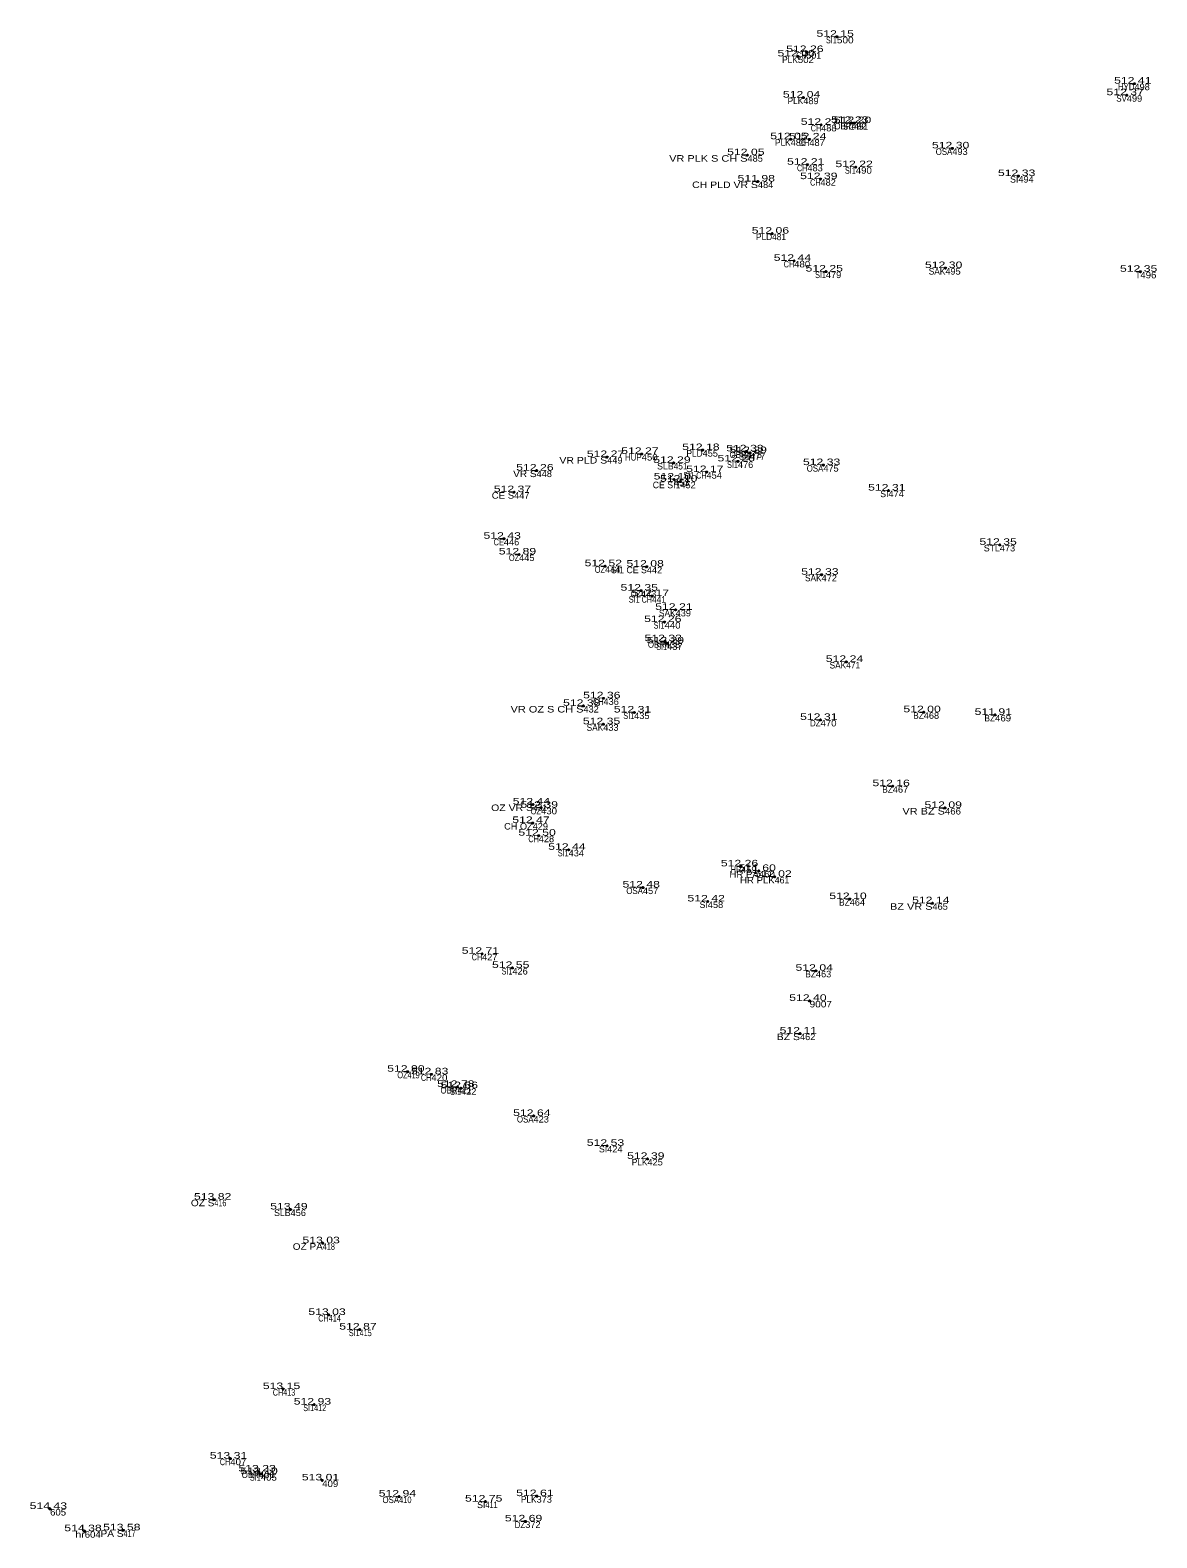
# Model space of a CAD drawing. Extents: x -643086 to -639283, y -1131805 to -1123269.
# Drawn here: x -639403.7 to -639352, y -1123478.6 to -1123409.5 of the extents above; entities that cross this region are included whole.
import ezdxf
from ezdxf.enums import TextEntityAlignment as Align

# ---------------------------------------------------------------- set-up
doc = ezdxf.new("R2010")
doc.units = 0
doc.header["$LTSCALE"] = 0.12
doc.header["$PDMODE"] = 32
doc.header["$PDSIZE"] = 0.06
for name, color, linetype in [('1', 7, 'Continuous'), ('2', 7, 'Continuous'), ('3', 7, 'Continuous'), ('4', 7, 'Continuous')]:
    doc.layers.add(name, color=color, linetype=linetype)

msp = doc.modelspace()

# ---------------------------------------------------------------- linework, layer by layer
at = {"layer": '1'}
for p in [(-639366.68, -1123409.77), (-639368.47, -1123410.67), (-639368.07, -1123410.47), (-639353.02, -1123411.92), (-639368.22, -1123412.56), (-639353.37, -1123412.45), (-639367.4, -1123413.81), (-639366.01, -1123413.72), (-639365.88, -1123413.73), (-639368.8, -1123414.47), (-639367.94, -1123414.48), (-639361.38, -1123414.89), (-639370.78, -1123415.2), (-639368.03, -1123415.64), (-639367.43, -1123416.3), (-639365.81, -1123415.75), (-639358.35, -1123416.16), (-639370.3, -1123416.41), (-639369.65, -1123418.8), (-639368.64, -1123420.05), (-639367.18, -1123420.54), (-639361.7, -1123420.38), (-639352.75, -1123420.55), (-639372.84, -1123428.73), (-639370.82, -1123428.79), (-639377.22, -1123429.05), (-639375.64, -1123428.91), (-639374.17, -1123429.32), (-639371.22, -1123429.25), (-639370.67, -1123428.87), (-639367.3, -1123429.42), (-639380.46, -1123429.67), (-639374.15, -1123430.08), (-639373.86, -1123430.18), (-639372.66, -1123429.74), (-639381.49, -1123430.66), (-639364.31, -1123430.59), (-639381.96, -1123432.8), (-639381.26, -1123433.52), (-639359.2, -1123433.08), (-639377.32, -1123434.06), (-639375.4, -1123434.08), (-639367.38, -1123434.45), (-639375.67, -1123435.18), (-639375.16, -1123435.43), (-639374.08, -1123436.06), (-639374.59, -1123436.62), (-639374.57, -1123437.5), (-639374.47, -1123437.6), (-639366.25, -1123438.45), (-639378.31, -1123440.47), (-639377.39, -1123440.12), (-639375.98, -1123440.77), (-639367.43, -1123441.11), (-639362.69, -1123440.76), (-639359.42, -1123440.88), (-639377.4, -1123441.31), (-639364.11, -1123444.15), (-639380.62, -1123444.99), (-639380.26, -1123445.14), (-639361.72, -1123445.15), (-639380.64, -1123445.84), (-639380.36, -1123446.42), (-639378.99, -1123447.07), (-639371.07, -1123447.83), (-639370.26, -1123448.04), (-639375.58, -1123448.8), (-639369.53, -1123448.31), (-639372.6, -1123449.44), (-639366.09, -1123449.33), (-639362.29, -1123449.52), (-639382.96, -1123451.84), (-639381.57, -1123452.49), (-639367.64, -1123452.62), (-639367.93, -1123454), (-639368.37, -1123455.5), (-639386.38, -1123457.25), (-639385.29, -1123457.37), (-639384.09, -1123457.95), (-639383.93, -1123458.01), (-639380.6, -1123459.28), (-639377.22, -1123460.65), (-639375.37, -1123461.25), (-639395.25, -1123463.12), (-639391.75, -1123463.57), (-639390.27, -1123465.12), (-639390, -1123468.41), (-639388.58, -1123469.08), (-639392.09, -1123471.81), (-639390.67, -1123472.52), (-639394.52, -1123475), (-639393.21, -1123475.59), (-639393.12, -1123475.71), (-639390.3, -1123476), (-639386.77, -1123476.74), (-639382.81, -1123476.97), (-639380.46, -1123476.72), (-639402.79, -1123477.31), (-639380.98, -1123477.88), (-639401.2, -1123478.33), (-639399.42, -1123478.29)]:
    msp.add_point(p, dxfattribs=at)

# ---------------------------------------------------------------- texts
at = {"layer": '2'}
for s, width, p in [('500', 1.15, (-639366.68, -1123410.07)), ('502', 1.1, (-639368.47, -1123410.97)), ('498', 1.05, (-639353.02, -1123412.22)), ('489', 1.05, (-639368.22, -1123412.86)), ('499', 1.05, (-639353.37, -1123412.75)), ('488', 1.05, (-639367.4, -1123414.11)), ('492', 1.05, (-639366.01, -1123414.02)), ('491', 0.95, (-639365.88, -1123414.03)), ('486', 1.05, (-639368.8, -1123414.77)), ('487', 1.05, (-639367.94, -1123414.78)), ('493', 1.05, (-639361.38, -1123415.19)), ('485', 1.05, (-639370.78, -1123415.5)), ('483', 1.05, (-639368.03, -1123415.94)), ('482', 1.05, (-639367.43, -1123416.6)), ('490', 1.1, (-639365.81, -1123416.05)), ('494', 1.05, (-639358.35, -1123416.46)), ('484', 1.05, (-639370.3, -1123416.71)), ('481', 0.95, (-639369.65, -1123419.1)), ('480', 1.1, (-639368.64, -1123420.35)), ('495', 1.05, (-639361.7, -1123420.68)), ('479', 1.05, (-639367.18, -1123420.84)), ('496', 1.1, (-639352.75, -1123420.85)), ('455', 1.05, (-639372.84, -1123429.03)), ('478', 1.05, (-639370.82, -1123429.09)), ('449', 1.05, (-639377.22, -1123429.35)), ('450', 1.1, (-639375.64, -1123429.21)), ('451', 0.95, (-639374.17, -1123429.62)), ('476', 1.05, (-639371.22, -1123429.55)), ('477', 1.05, (-639370.67, -1123429.17)), ('475', 1.05, (-639367.3, -1123429.72)), ('448', 1.05, (-639380.46, -1123429.97)), ('453', 1.05, (-639374.15, -1123430.38)), ('452', 1.05, (-639373.86, -1123430.48)), ('454', 1.05, (-639372.66, -1123430.04)), ('447', 1.05, (-639381.49, -1123430.96)), ('474', 1.05, (-639364.31, -1123430.89)), ('446', 1.05, (-639381.96, -1123433.1)), ('445', 1.05, (-639381.26, -1123433.82)), ('473', 1.05, (-639359.2, -1123433.38)), ('444', 1.05, (-639377.32, -1123434.36)), ('442', 1.05, (-639375.4, -1123434.38)), ('472', 1.05, (-639367.38, -1123434.75)), ('443', 1.05, (-639375.67, -1123435.48)), ('441', 0.95, (-639375.16, -1123435.73)), ('439', 1.05, (-639374.08, -1123436.36)), ('440', 1.1, (-639374.59, -1123436.92)), ('438', 1.05, (-639374.57, -1123437.8)), ('437', 1.05, (-639374.47, -1123437.9)), ('471', 0.95, (-639366.25, -1123438.75)), ('432', 1.05, (-639378.31, -1123440.77)), ('436', 1.05, (-639377.39, -1123440.42)), ('435', 1.05, (-639375.98, -1123441.07)), ('470', 1.1, (-639367.43, -1123441.41)), ('468', 1.05, (-639362.69, -1123441.06)), ('469', 1.1, (-639359.42, -1123441.18)), ('433', 1.05, (-639377.4, -1123441.61)), ('467', 1.05, (-639364.11, -1123444.45)), ('431', 0.95, (-639380.62, -1123445.29)), ('430', 1.1, (-639380.26, -1123445.44)), ('466', 1.1, (-639361.72, -1123445.45)), ('429', 1.05, (-639380.64, -1123446.14)), ('428', 1.05, (-639380.36, -1123446.72)), ('434', 1.05, (-639378.99, -1123447.37)), ('459', 1.05, (-639371.07, -1123448.13)), ('460', 1.1, (-639370.26, -1123448.34)), ('457', 1.05, (-639375.58, -1123449.1)), ('458', 1.05, (-639372.6, -1123449.74)), ('464', 1.05, (-639366.09, -1123449.63)), ('465', 1.05, (-639362.29, -1123449.82)), ('427', 1.05, (-639382.96, -1123452.14)), ('426', 1.05, (-639381.57, -1123452.79)), ('463', 1.05, (-639367.64, -1123452.92)), ('9007', 1.15, (-639367.93, -1123454.3)), ('462', 1.05, (-639368.37, -1123455.8)), ('419', 0.8, (-639386.38, -1123457.55)), ('420', 1.1, (-639385.29, -1123457.67)), ('421', 0.95, (-639384.09, -1123458.25)), ('422', 1.05, (-639383.93, -1123458.31)), ('423', 1.05, (-639380.6, -1123459.58)), ('424', 1.05, (-639377.22, -1123460.95)), ('425', 1.05, (-639375.37, -1123461.55)), ('416', 0.8, (-639395.25, -1123463.42)), ('456', 1.05, (-639391.75, -1123463.87)), ('418', 0.8, (-639390.27, -1123465.42)), ('414', 0.8, (-639390, -1123468.71)), ('415', 0.8, (-639388.58, -1123469.38)), ('413', 0.8, (-639392.09, -1123472.11)), ('412', 0.8, (-639390.67, -1123472.82)), ('407', 1.1, (-639394.52, -1123475.3)), ('406', 1.1, (-639393.21, -1123475.89)), ('405', 1.1, (-639393.12, -1123476.01)), ('409', 1.1, (-639390.3, -1123476.3)), ('410', 0.85, (-639386.77, -1123477.04)), ('411', 0.7, (-639382.81, -1123477.27)), ('373', 1.05, (-639380.46, -1123477.02)), ('605', 1.1, (-639402.79, -1123477.61)), ('372', 1.05, (-639380.98, -1123478.18)), ('604', 1.1, (-639401.2, -1123478.63)), ('417', 0.8, (-639399.42, -1123478.59))]:
    msp.add_text(s, height=0.3, dxfattribs=dict(at, width=width)).set_placement(p)
for s, p in [('501', (-639368.07, -1123410.77)), ('461', (-639369.53, -1123448.61))]:
    msp.add_text(s, height=0.3, dxfattribs=at).set_placement(p)
at = {"layer": '3', "width": 1.4}
for s, p in [('512 15 ', (-639366.68, -1123409.77)), ('512 00 ', (-639368.47, -1123410.67)), ('512 26 ', (-639368.07, -1123410.47)), ('512 37 ', (-639353.37, -1123412.45)), ('512 41 ', (-639353.02, -1123411.92)), ('512 04 ', (-639368.22, -1123412.56)), ('512 27 ', (-639367.4, -1123413.81)), ('512 23 ', (-639366.01, -1123413.72)), ('512 20 ', (-639365.88, -1123413.73)), ('512 05 ', (-639368.8, -1123414.47)), ('512 24 ', (-639367.94, -1123414.48)), ('512 05 ', (-639370.78, -1123415.2)), ('512 30 ', (-639361.38, -1123414.89)), ('512 21 ', (-639368.03, -1123415.64)), ('512 22 ', (-639365.81, -1123415.75)), ('511 98 ', (-639370.3, -1123416.41)), ('512 39 ', (-639367.43, -1123416.3)), ('512 33 ', (-639358.35, -1123416.16)), ('512 06 ', (-639369.65, -1123418.8)), ('512 44 ', (-639368.64, -1123420.05)), ('512 25 ', (-639367.18, -1123420.54)), ('512 30 ', (-639361.7, -1123420.38)), ('512 35 ', (-639352.75, -1123420.55)), ('512 27 ', (-639377.22, -1123429.05)), ('512 27 ', (-639375.64, -1123428.91)), ('512 18 ', (-639372.84, -1123428.73)), ('512 33 ', (-639370.82, -1123428.79)), ('512 29 ', (-639370.67, -1123428.87)), ('512 26 ', (-639380.46, -1123429.67)), ('512 29 ', (-639374.17, -1123429.32)), ('512 17 ', (-639372.66, -1123429.74)), ('512 26 ', (-639371.22, -1123429.25)), ('512 33 ', (-639367.3, -1123429.42)), ('512 10 ', (-639374.15, -1123430.08)), ('512 10 ', (-639373.86, -1123430.18)), ('512 37 ', (-639381.49, -1123430.66)), ('512 31 ', (-639364.31, -1123430.59)), ('512 43 ', (-639381.96, -1123432.8)), ('512 35 ', (-639359.2, -1123433.08)), ('512 89 ', (-639381.26, -1123433.52)), ('512 52 ', (-639377.32, -1123434.06)), ('512 08 ', (-639375.4, -1123434.08)), ('512 33 ', (-639367.38, -1123434.45)), ('512 35 ', (-639375.67, -1123435.18)), ('512 17 ', (-639375.16, -1123435.43)), ('512 26 ', (-639374.59, -1123436.62)), ('512 21 ', (-639374.08, -1123436.06)), ('512 33 ', (-639374.57, -1123437.5)), ('512 29 ', (-639374.47, -1123437.6)), ('512 24 ', (-639366.25, -1123438.45)), ('512 36 ', (-639377.39, -1123440.12)), ('512 38 ', (-639378.31, -1123440.47)), ('512 31 ', (-639375.98, -1123440.77)), ('512 00 ', (-639362.69, -1123440.76)), ('511 91 ', (-639359.42, -1123440.88)), ('512 35 ', (-639377.4, -1123441.31)), ('512 31 ', (-639367.43, -1123441.11)), ('512 16 ', (-639364.11, -1123444.15)), ('512 44 ', (-639380.62, -1123444.99)), ('512 39 ', (-639380.26, -1123445.14)), ('512 09 ', (-639361.72, -1123445.15)), ('512 47 ', (-639380.64, -1123445.84)), ('512 50 ', (-639380.36, -1123446.42)), ('512 44 ', (-639378.99, -1123447.07)), ('512 26 ', (-639371.07, -1123447.83)), ('511 60 ', (-639370.26, -1123448.04)), ('512 02 ', (-639369.53, -1123448.31)), ('512 48 ', (-639375.58, -1123448.8)), ('512 42 ', (-639372.6, -1123449.44)), ('512 10 ', (-639366.09, -1123449.33)), ('512 14 ', (-639362.29, -1123449.52)), ('512 71 ', (-639382.96, -1123451.84)), ('512 55 ', (-639381.57, -1123452.49)), ('512 04 ', (-639367.64, -1123452.62)), ('512 40 ', (-639367.93, -1123454)), ('512 11 ', (-639368.37, -1123455.5)), ('512 90 ', (-639386.38, -1123457.25)), ('512 83 ', (-639385.29, -1123457.37)), ('512 78 ', (-639384.09, -1123457.95)), ('512 66 ', (-639383.93, -1123458.01)), ('512 64 ', (-639380.6, -1123459.28)), ('512 53 ', (-639377.22, -1123460.65)), ('512 39 ', (-639375.37, -1123461.25)), ('513 82 ', (-639395.25, -1123463.12)), ('513 49 ', (-639391.75, -1123463.57)), ('513 03 ', (-639390.27, -1123465.12)), ('513 03 ', (-639390, -1123468.41)), ('512 87 ', (-639388.58, -1123469.08)), ('513 15 ', (-639392.09, -1123471.81)), ('512 93 ', (-639390.67, -1123472.52)), ('513 31 ', (-639394.52, -1123475)), ('513 23 ', (-639393.21, -1123475.59)), ('513 10 ', (-639393.12, -1123475.71)), ('513 01 ', (-639390.3, -1123476)), ('512 94 ', (-639386.77, -1123476.74)), ('512 61 ', (-639380.46, -1123476.72)), ('514 43 ', (-639402.79, -1123477.31)), ('512 75 ', (-639382.81, -1123476.97)), ('512 69 ', (-639380.98, -1123477.88)), ('514 38 ', (-639401.2, -1123478.33)), ('513 58 ', (-639399.42, -1123478.29))]:
    msp.add_text(s, height=0.3, dxfattribs=at).set_placement(p, align=Align.CENTER)
at = {"layer": '4'}
for s, width, p in [('SI1', 0.8, (-639366.68, -1123410.07)), ('PLK', 0.95, (-639368.47, -1123410.97)), ('CH', 0.8, (-639368.07, -1123410.77)), ('HYD', 0.9, (-639353.02, -1123412.22)), ('PLK', 0.95, (-639368.22, -1123412.86)), ('SV', 0.9, (-639353.37, -1123412.75)), ('CH', 0.8, (-639367.4, -1123414.11)), ('OBR', 0.9, (-639366.01, -1123414.02)), ('SI1', 0.8, (-639365.88, -1123414.03)), ('PLK', 0.95, (-639368.8, -1123414.77)), ('CH', 0.8, (-639367.94, -1123414.78)), ('OSA', 0.9, (-639361.38, -1123415.19)), ('VR PLK S CH S', 1.25, (-639370.78, -1123415.5)), ('CH', 0.8, (-639368.03, -1123415.94)), ('CH', 0.8, (-639367.43, -1123416.6)), ('SI1', 0.8, (-639365.81, -1123416.05)), ('CH PLD VR S', 1.2, (-639370.3, -1123416.71)), ('PLD', 0.95, (-639369.65, -1123419.1)), ('CH', 0.8, (-639368.64, -1123420.35)), ('SAK', 0.95, (-639361.7, -1123420.68)), ('SI1', 0.8, (-639367.18, -1123420.84)), ('T', 0.8, (-639352.75, -1123420.85)), ('PLD', 0.95, (-639372.84, -1123429.03)), ('OBR', 0.9, (-639370.82, -1123429.09)), ('VR PLD S', 1.2, (-639377.22, -1123429.35)), ('HUP', 0.9, (-639375.64, -1123429.21)), ('SI1', 0.8, (-639371.22, -1123429.55)), ('SI1', 0.8, (-639370.67, -1123429.17)), ('OSA', 0.9, (-639367.3, -1123429.72)), ('VR S', 1.15, (-639380.46, -1123429.97)), ('SI1 CH', 0.8, (-639372.66, -1123430.04)), ('CE S', 1.1, (-639381.49, -1123430.96)), ('CE', 0.85, (-639381.96, -1123433.1)), ('OZ', 0.85, (-639381.26, -1123433.82)), ('OZ', 0.85, (-639377.32, -1123434.36)), ('SAK', 0.95, (-639367.38, -1123434.75)), ('SI1 CH', 0.8, (-639375.16, -1123435.73)), ('OZ', 0.85, (-639375.67, -1123435.48)), ('SAK', 0.95, (-639374.08, -1123436.36)), ('SI1', 0.8, (-639374.59, -1123436.92)), ('OBR', 0.9, (-639374.57, -1123437.8)), ('SI1', 0.8, (-639374.47, -1123437.9)), ('SAK', 0.95, (-639366.25, -1123438.75)), ('VR OZ S CH S', 1.25, (-639378.31, -1123440.77)), ('CH', 0.8, (-639377.39, -1123440.42)), ('SI1', 0.8, (-639375.98, -1123441.07)), ('DZ', 0.9, (-639367.43, -1123441.41)), ('BZ', 0.95, (-639362.69, -1123441.06)), ('BZ', 0.95, (-639359.42, -1123441.18)), ('SAK', 0.95, (-639377.4, -1123441.61)), ('BZ', 0.95, (-639364.11, -1123444.45)), ('OZ VR S', 1.2, (-639380.62, -1123445.29)), ('OZ', 0.85, (-639380.26, -1123445.44)), ('VR BZ S', 1.25, (-639361.72, -1123445.45)), ('CH OZ', 1.05, (-639380.64, -1123446.14)), ('CH', 0.8, (-639380.36, -1123446.72)), ('SI1', 0.8, (-639378.99, -1123447.37)), ('HR PA', 1.1, (-639370.26, -1123448.34)), ('HR', 0.8, (-639371.07, -1123448.13)), ('OSA', 0.9, (-639375.58, -1123449.1)), ('HR PLK', 1.1, (-639369.53, -1123448.61)), ('BZ', 0.95, (-639366.09, -1123449.63)), ('BZ VR S', 1.25, (-639362.29, -1123449.82)), ('CH', 0.8, (-639382.96, -1123452.14)), ('SI1', 0.8, (-639381.57, -1123452.79)), ('BZ', 0.95, (-639367.64, -1123452.92)), ('BZ S', 1.2, (-639368.37, -1123455.8)), ('OZ', 0.85, (-639386.38, -1123457.55)), ('CH', 0.8, (-639385.29, -1123457.67)), ('OBR', 0.9, (-639384.09, -1123458.25)), ('SI1', 0.8, (-639383.93, -1123458.31)), ('OSA', 0.9, (-639380.6, -1123459.58)), ('PLK', 0.95, (-639375.37, -1123461.55)), ('OZ S', 1.15, (-639395.25, -1123463.42)), ('OZ PA', 1.15, (-639390.27, -1123465.42)), ('CH', 0.8, (-639390, -1123468.71)), ('SI1', 0.8, (-639388.58, -1123469.38)), ('CH', 0.8, (-639392.09, -1123472.11)), ('SI1', 0.8, (-639390.67, -1123472.82)), ('CH', 0.8, (-639394.52, -1123475.3)), ('OBR', 0.9, (-639393.21, -1123475.89)), ('SI1', 0.8, (-639393.12, -1123476.01)), ('OSA', 0.9, (-639386.77, -1123477.04)), ('PLK', 0.95, (-639380.46, -1123477.02)), ('DZ', 0.9, (-639380.98, -1123478.18)), ('hr', 1.2, (-639401.2, -1123478.63)), ('PA S', 1.15, (-639399.42, -1123478.59))]:
    msp.add_text(s, height=0.3, dxfattribs=dict(at, width=width)).set_placement(p, align=Align.RIGHT)
for s, p in [('SI', (-639358.35, -1123416.46)), ('SLB', (-639374.17, -1123429.62)), ('CE SI1', (-639373.86, -1123430.48)), ('SI', (-639364.31, -1123430.89)), ('STL', (-639359.2, -1123433.38)), ('SI1 CE S', (-639375.4, -1123434.38)), ('SI', (-639372.6, -1123449.74)), ('SI', (-639377.22, -1123460.95)), ('SLB', (-639391.75, -1123463.87)), ('SI', (-639382.81, -1123477.27))]:
    msp.add_text(s, height=0.3, dxfattribs=at).set_placement(p, align=Align.RIGHT)

doc.saveas('drawing.dxf')
